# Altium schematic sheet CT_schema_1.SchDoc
size 526 x 318 mm
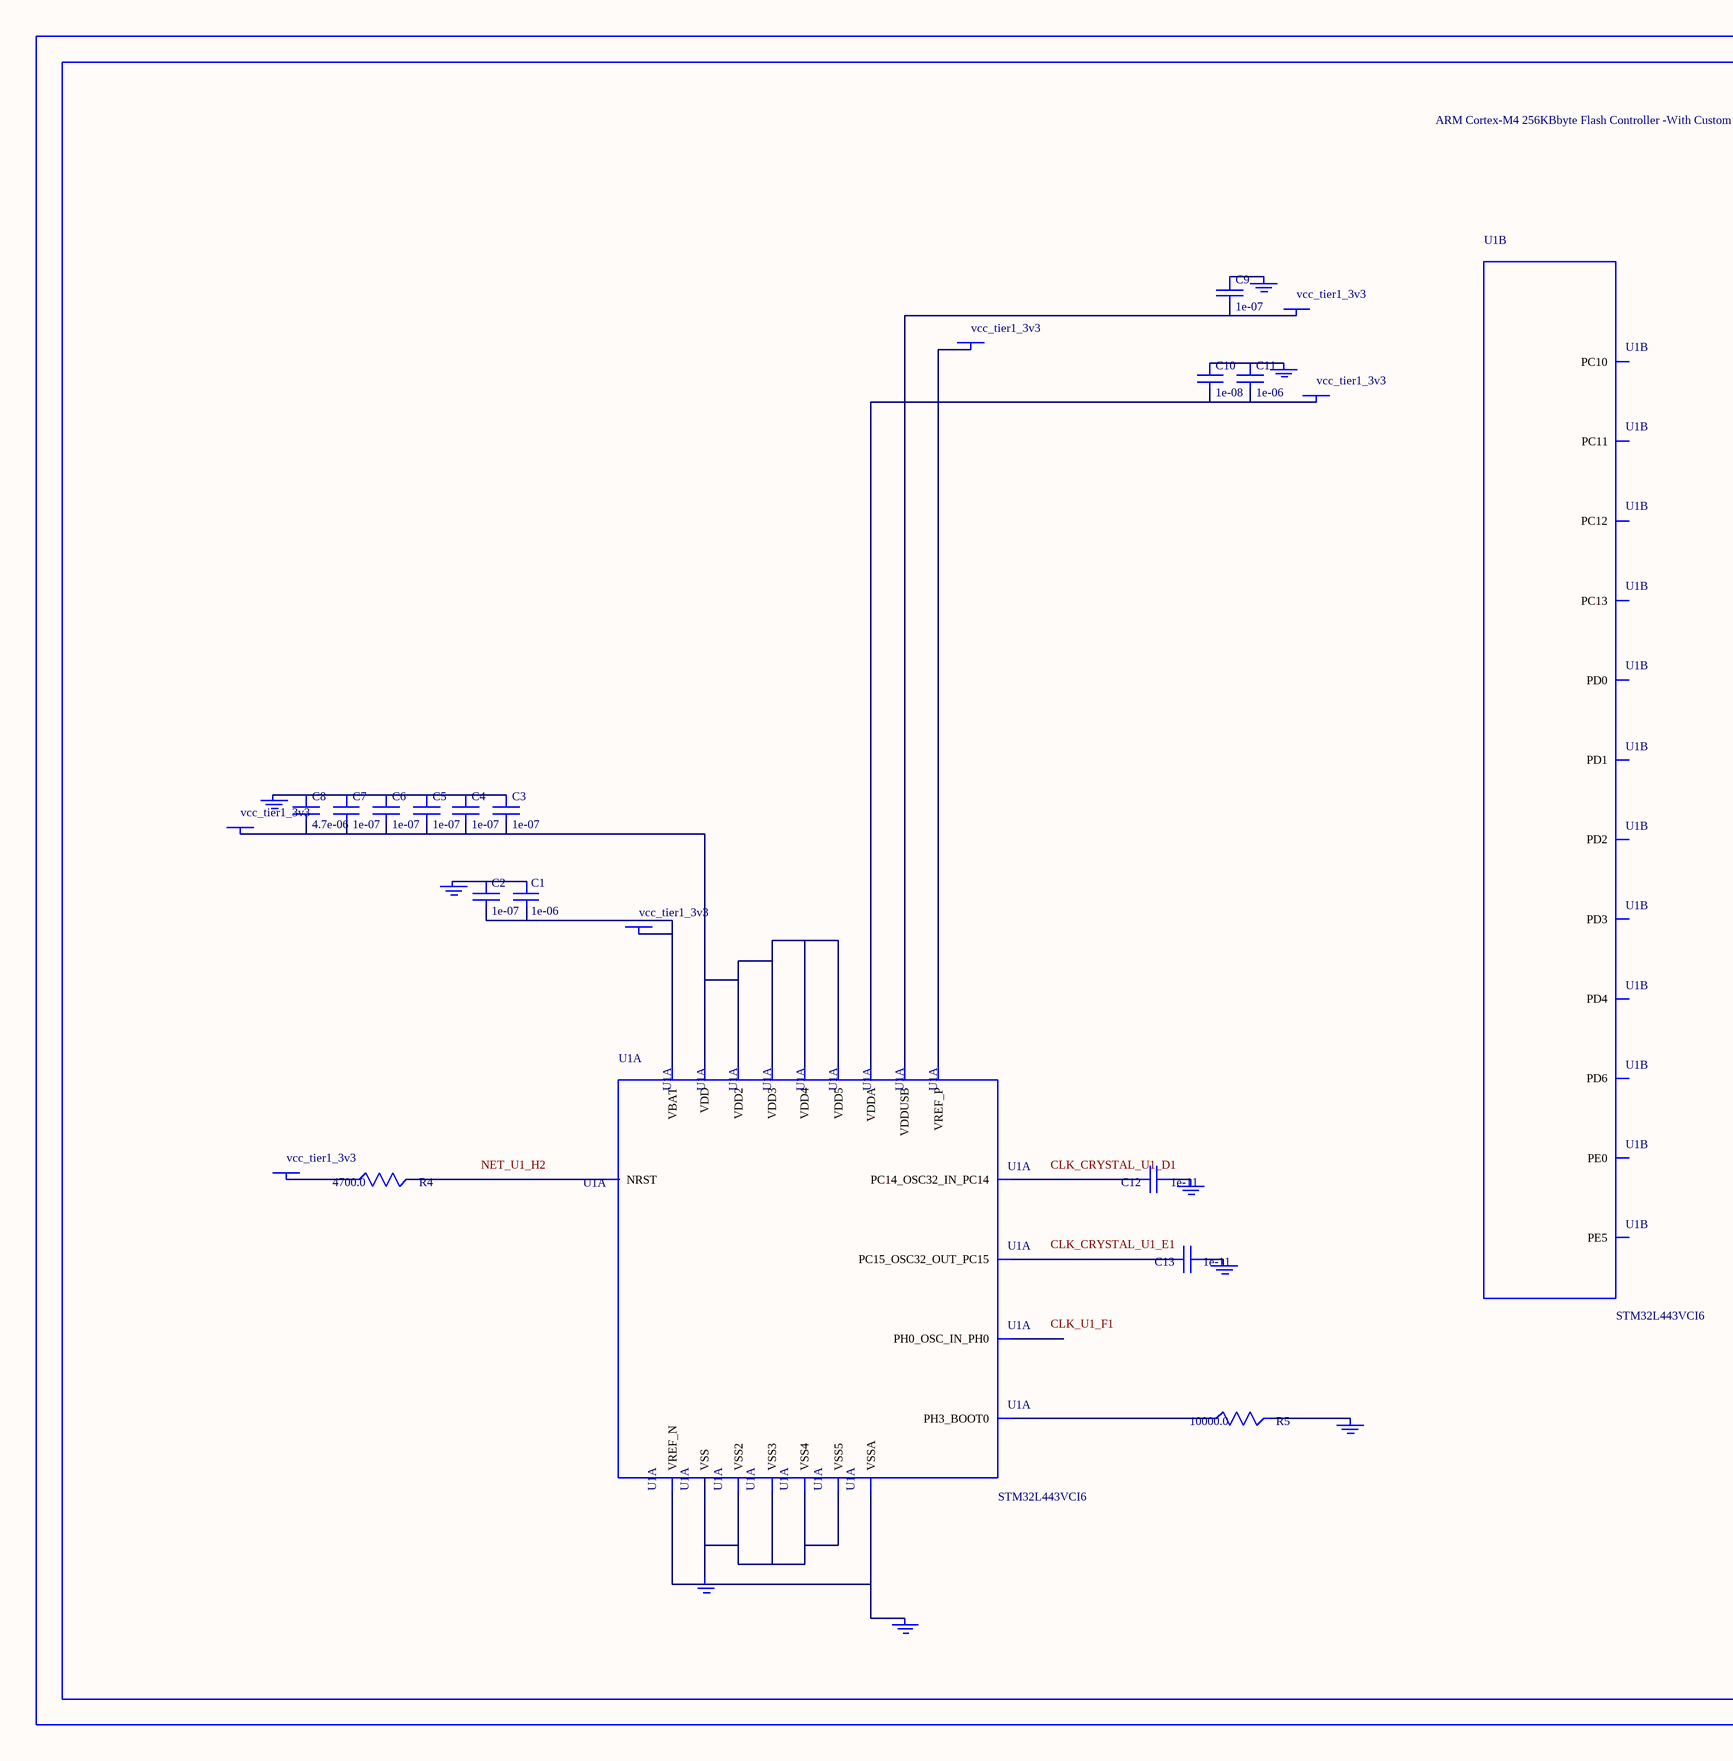
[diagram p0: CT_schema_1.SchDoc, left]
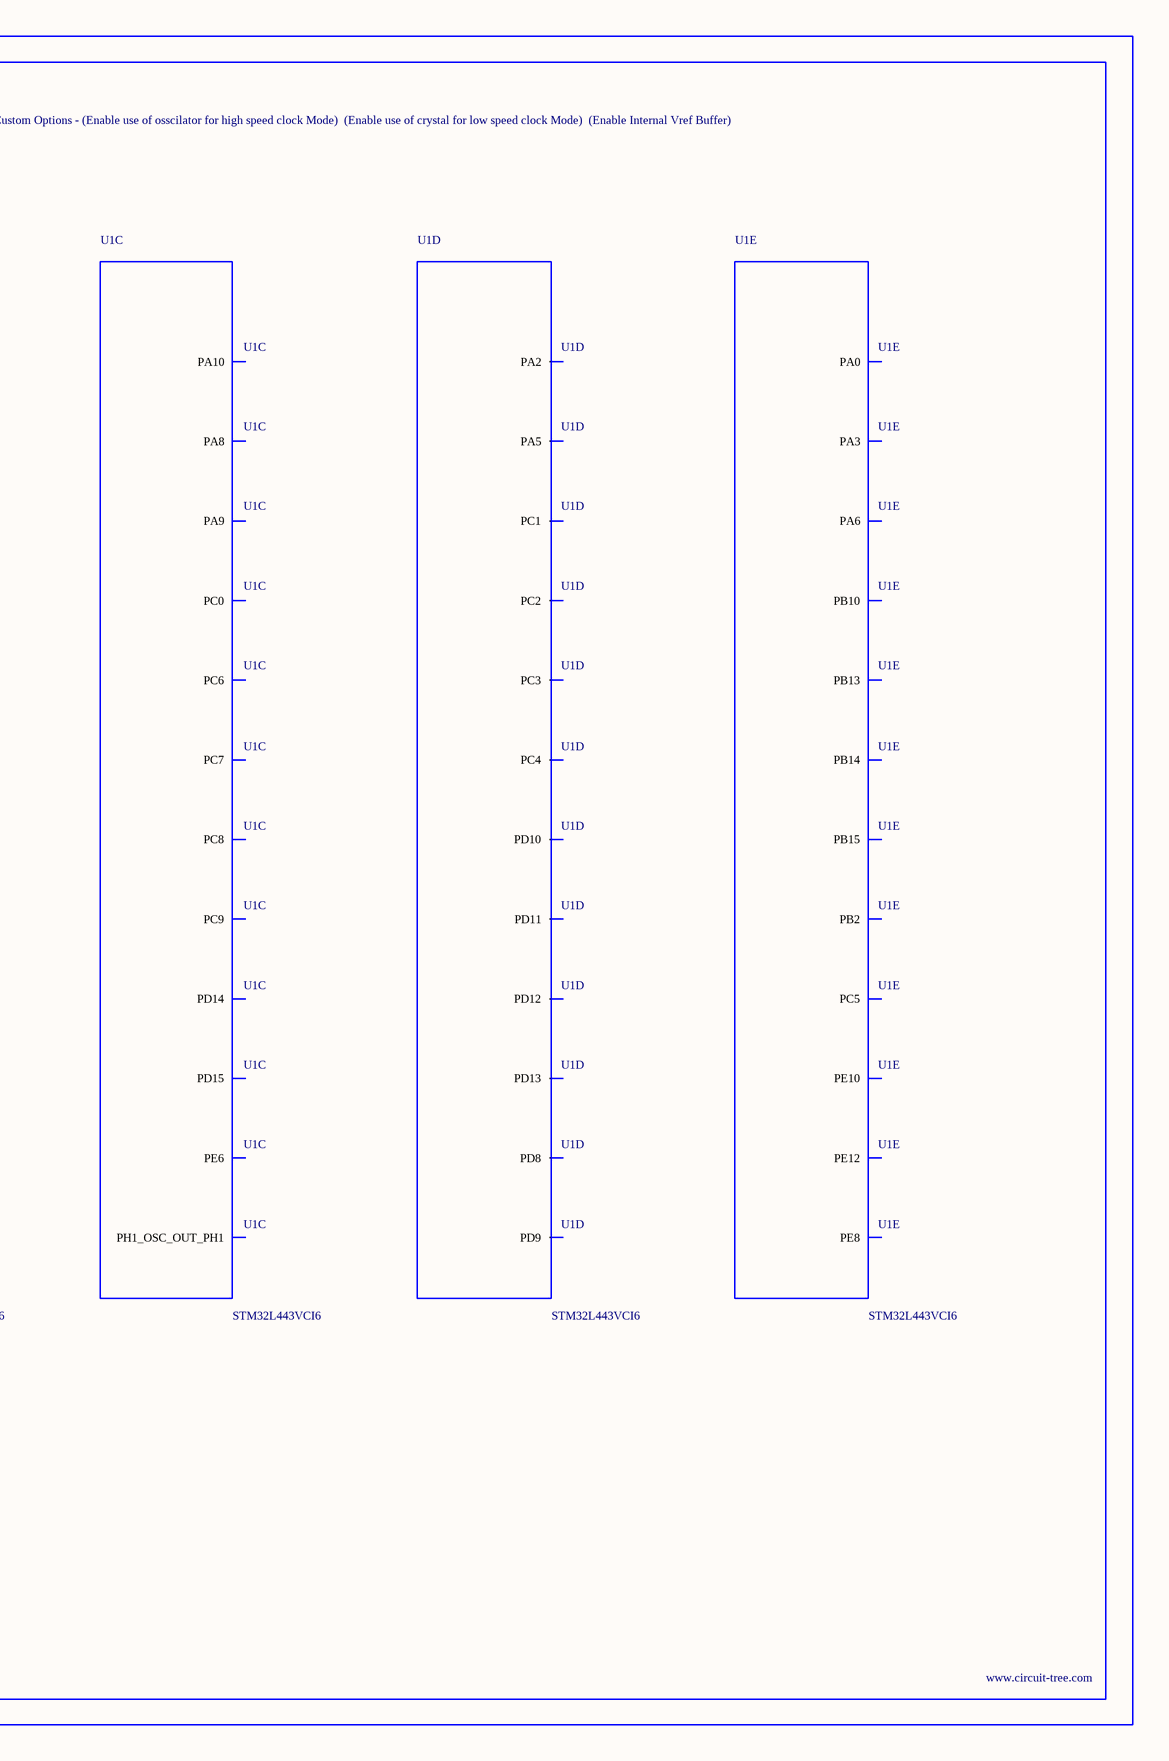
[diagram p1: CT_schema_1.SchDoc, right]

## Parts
BORDER0  (no value)
C1  1e-06  [C0603]
C2  1e-07  [C0603]
C3  1e-07  [C0603]
C4  1e-07  [C0603]
C5  1e-07  [C0603]
C6  1e-07  [C0603]
C7  1e-07  [C0603]
C8  4.7e-06  [C0603]
C9  1e-07  [C0603]
C10  1e-08  [C0603]
C11  1e-06  [C0603]
C12  1e-11  [C0402]
C13  1e-11  [C0402]
GND_INSTANCE_0_0  (no value)
GND_INSTANCE_0_1  (no value)
GND_INSTANCE_0_2  (no value)
GND_INSTANCE_0_3  (no value)
GND_INSTANCE_0_4  (no value)
GND_INSTANCE_0_5  (no value)
GND_INSTANCE_0_6  (no value)
GND_INSTANCE_0_7  (no value)
GND_INSTANCE_0_8  (no value)
POWER_INSTANCE_0_0  vcc_tier1_3v3
POWER_INSTANCE_0_1  vcc_tier1_3v3
POWER_INSTANCE_0_2  vcc_tier1_3v3
POWER_INSTANCE_0_3  vcc_tier1_3v3
POWER_INSTANCE_0_4  vcc_tier1_3v3
POWER_INSTANCE_0_5  vcc_tier1_3v3
R4  4700.0  [R0603]
R5  10000.0  [R0603]
U1  STM32L443VCI6  [UFBGA100]  (parts A,B,C,D,E of 7)

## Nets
NetC1_1: C1.1 C2.1 GND_INSTANCE_0_0.0(GND)
NetC1_2: C1.2 C2.2 POWER_INSTANCE_0_0.0(PWR) U1.E2(VBAT)
NetC3_1: C3.1 C4.1 C5.1 C6.1 C7.1 C8.1 GND_INSTANCE_0_1.0(GND)
NetC3_2: C3.2 C4.2 C5.2 C6.2 C7.2 C8.2 POWER_INSTANCE_0_1.0(PWR) U1.C4(VDD) U1.G2(VDD4) U1.G11(VDD2) U1.G12(VDD3) U1.H3(VDD5)
NetC9_1: C9.1 GND_INSTANCE_0_3.0(GND)
NetC9_2: C9.2 POWER_INSTANCE_0_2.0(PWR) U1.C11(VDDUSB)
NetC10_1: C10.1 C11.1 GND_INSTANCE_0_4.0(GND)
NetC10_2: C10.2 C11.2 POWER_INSTANCE_0_3.0(PWR) U1.M1(VDDA)
NetC12_1: C12.1 GND_INSTANCE_0_5.0(GND)
NetC12_2: C12.2 U1.D1(PC14_OSC32_IN_PC14)
NetC13_1: C13.1 GND_INSTANCE_0_6.0(GND)
NetC13_2: C13.2 U1.E1(PC15_OSC32_OUT_PC15)
NetGND_INSTANCE_0_2_0: GND_INSTANCE_0_2.0(GND) R5.2
NetGND_INSTANCE_0_7_0: GND_INSTANCE_0_7.0(GND) U1.J1(VSSA) U1.K1(VREF_N)
NetGND_INSTANCE_0_8_0: GND_INSTANCE_0_8.0(GND) U1.D3(VSS) U1.E3(VSS2) U1.F2(VSS5) U1.F11(VSS3) U1.F12(VSS4)
NetPOWER_INSTANCE_0_4_0: POWER_INSTANCE_0_4.0(PWR) U1.L1(VREF_P)
NetPOWER_INSTANCE_0_5_0: POWER_INSTANCE_0_5.0(PWR) R4.1
NetR4_2: R4.2 U1.H2(NRST)
NetR5_1: R5.1 U1.A4(PH3_BOOT0)

Not connected (* = marked no-connect by the designer): U1 B6(PD6) B7(PD4) B8(PD3) B9(PD1) B10(PC12) B11(PC10) C1(PC13) C2(PE5) C3(PE0) C8(PD2) C9(PD0) C10(PC11) C12(PA10) D2(PE6) D10(PA9) D11(PA8) D12(PC9) E10(PC8) E11(PC7) E12(PC6) F1(PH0_OSC_IN_PH0) G1(PH1_OSC_OUT_PH1) H1(PC0) H10(PD15) H11(PD14) H12(PD13) J2(PC1) J3(PC2) J10(PD12) J11(PD11) J12(PD10) K2(PC3) K3(PA2) K4(PA5) K5(PC4) K8(PD9) K9(PD8) K10(PB15) K11(PB14) K12(PB13) L2(PA0) L3(PA3) L4(PA6) L5(PC5) L6(PB2) L7(PE8) L8(PE10) L9(PE12) L10(PB10)

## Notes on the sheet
- Labels drawn without touching a wire or pin: CLK_CRYSTAL_U1_D1, CLK_CRYSTAL_U1_E1, CLK_U1_F1, NET_U1_H2

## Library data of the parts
BORDER0 = BORDER_PAGE0
C1 C11 = C0603C105K3RACTU
C2-C7 C9 = 06035C104K4Z2A
C8 = GRM188R6YA475KE15D
C10 = 06035C103K4Z2A
C12 C13 = C0402C100K3GACTU
GND_INSTANCE_0_0-GND_INSTANCE_0_8 = GND
POWER_INSTANCE_0_0-POWER_INSTANCE_0_5 = PWR
R4 = RC0603JR-074K7L
R5 = RC0603JR-0710KL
